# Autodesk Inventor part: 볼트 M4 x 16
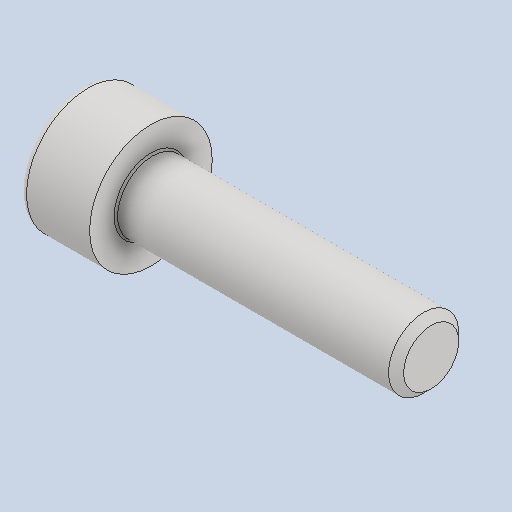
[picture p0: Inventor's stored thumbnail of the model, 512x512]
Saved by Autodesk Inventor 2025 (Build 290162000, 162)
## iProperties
Created: 2025-08
Part Number: 볼트 M4 x 16
Material: 스테인리스강
Description: 6각 소켓 머리 캡 나사
Document SubType Name: Modeling
Designer: infra028
Density: 8.08 g/cm^3
Appearance: 기본값
Author: jhkim
Sending System: Autodesk Inventor 2026
Preprocessor: ST-DEVELOPER v20.1
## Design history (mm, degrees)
feature "Solid1"
node "솔리드1"
